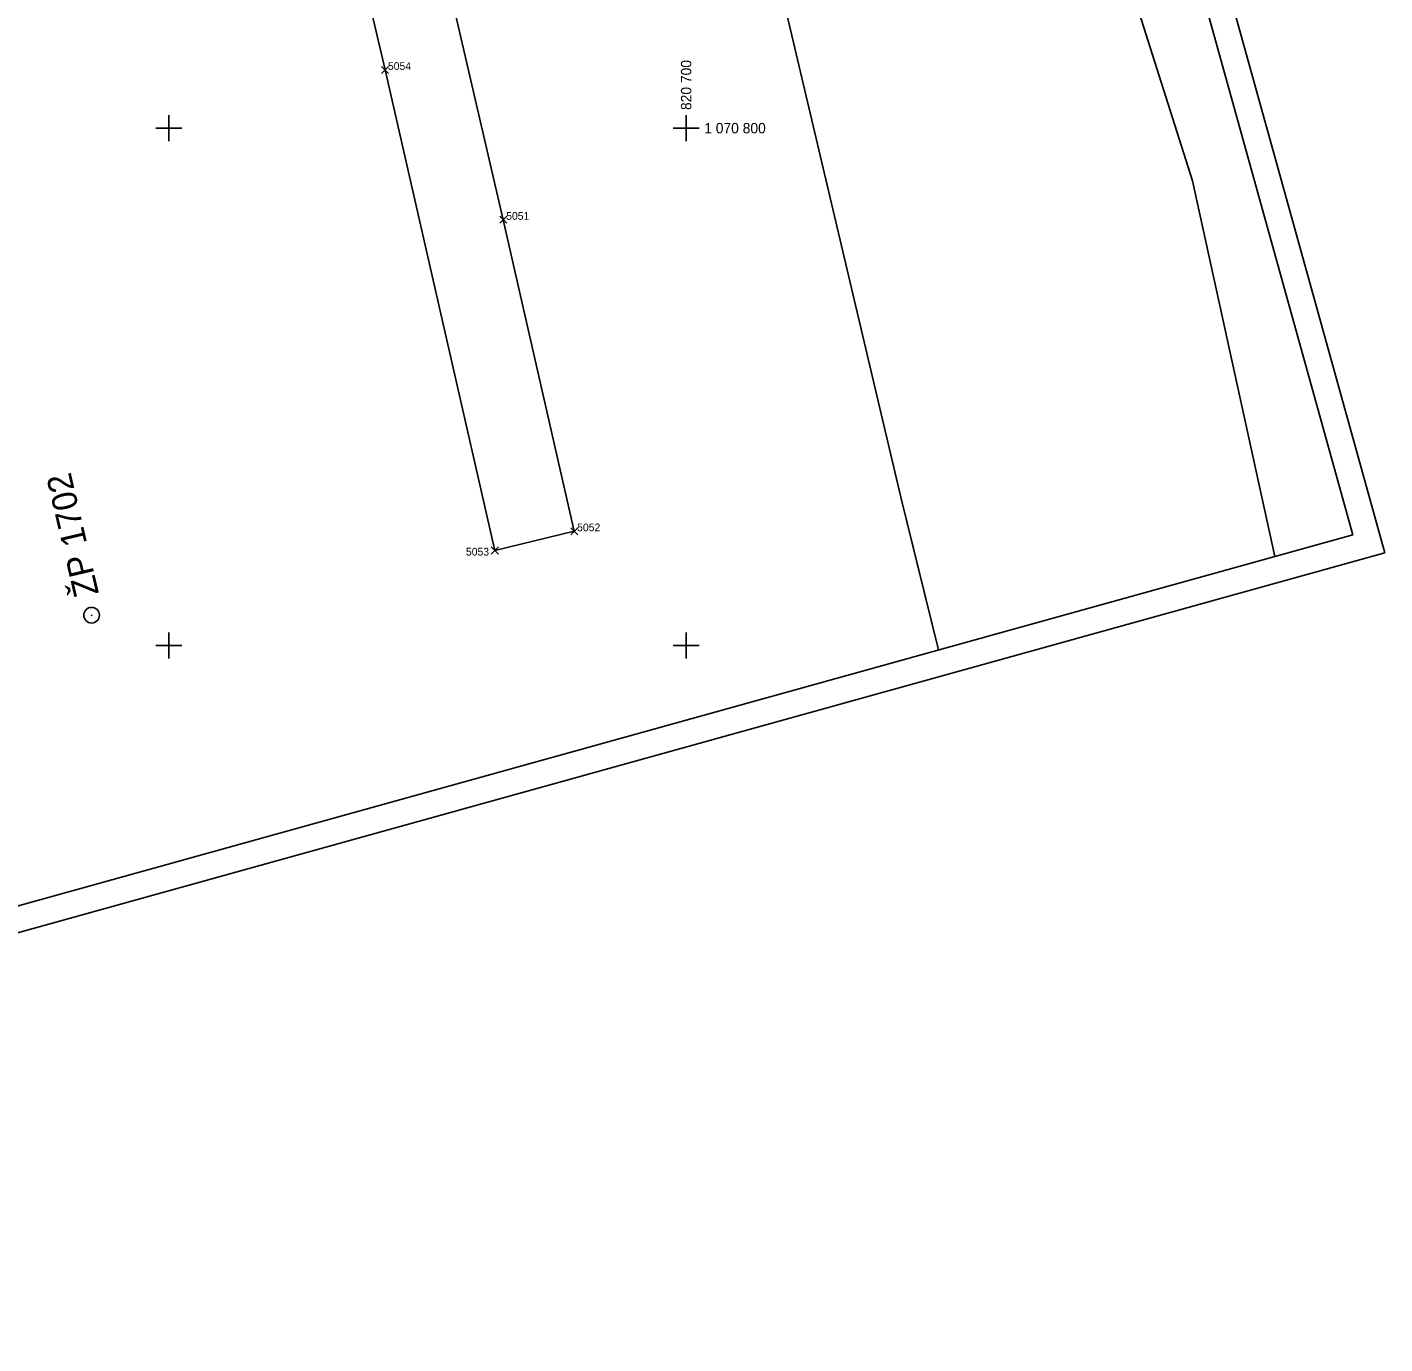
# Model space of a CAD drawing. Extents: x -821172 to -820632, y -1070921 to -1069931.
# Drawn here: x -820763.7 to -820632.5, y -1070917.5 to -1070790.2 of the extents above; entities that cross this region are included whole.
import ezdxf

# ---------------------------------------------------------------- set-up
doc = ezdxf.new("R2010")
doc.units = 0
for name, color, linetype in [('Ram', 7, 'Continuous'), ('Sit', 7, 'Continuous'), ('VB_bod_DZ', 7, 'Continuous'), ('Vrstva 52', 7, 'Continuous'), ('Vrstva 53', 7, 'Continuous'), ('Vrstva 55', 7, 'Continuous'), ('ZBP', 7, 'Continuous')]:
    doc.layers.add(name, color=color, linetype=linetype)

msp = doc.modelspace()

# ---------------------------------------------------------------- linework, layer by layer
at = {"layer": 'Ram'}
for points in [[(-820857.35, -1070031.72), (-820632.46, -1070841.06)], [(-820859.09, -1070034.8), (-820635.54, -1070839.32), (-820916.88, -1070917.49)], [(-820632.46, -1070841.06), (-820775.54, -1070880.81)]]:
    msp.add_lwpolyline(points, dxfattribs=at)
at = {"layer": 'Sit'}
for p, q in [((-820750, -1070798.75), (-820750, -1070800)), ((-820700, -1070798.75), (-820700, -1070800)), ((-820751.25, -1070800), (-820750, -1070800)), ((-820748.75, -1070800), (-820750, -1070800)), ((-820750, -1070801.25), (-820750, -1070800)), ((-820701.25, -1070800), (-820700, -1070800)), ((-820698.75, -1070800), (-820700, -1070800)), ((-820700, -1070801.25), (-820700, -1070800)), ((-820750, -1070848.75), (-820750, -1070850)), ((-820700, -1070848.75), (-820700, -1070850)), ((-820751.25, -1070850), (-820750, -1070850)), ((-820748.75, -1070850), (-820750, -1070850)), ((-820750, -1070851.25), (-820750, -1070850)), ((-820701.25, -1070850), (-820700, -1070850)), ((-820698.75, -1070850), (-820700, -1070850)), ((-820700, -1070851.25), (-820700, -1070850))]:
    msp.add_line(p, q, dxfattribs=at)
at = {"layer": 'VB_bod_DZ'}
for p, q in [((-820729.44, -1070794.72), (-820728.76, -1070794.04)), ((-820728.76, -1070794.72), (-820729.44, -1070794.04)), ((-820718.01, -1070809.2), (-820717.33, -1070808.52)), ((-820717.33, -1070809.2), (-820718.01, -1070808.52)), ((-820711.15, -1070839.31), (-820710.47, -1070838.62)), ((-820710.47, -1070839.31), (-820711.15, -1070838.62)), ((-820718.83, -1070841.17), (-820718.15, -1070840.48)), ((-820718.15, -1070841.17), (-820718.83, -1070840.48))]:
    msp.add_line(p, q, dxfattribs=at)
at = {"layer": 'Vrstva 52'}
msp.add_lwpolyline([(-820753.84, -1070657.98), (-820750.47, -1070669.89), (-820746.26, -1070680.97), (-820737.78, -1070703.32), (-820734.63, -1070715.91), (-820728.44, -1070746.18), (-820726.51, -1070765.13), (-820725.16, -1070774.41), (-820722.68, -1070787.32), (-820717.67, -1070808.86), (-820710.81, -1070838.96), (-820718.49, -1070840.82), (-820729.1, -1070794.38), (-820755.08, -1070683.79), (-820766.7, -1070635.67)], dxfattribs=at)
at = {"layer": 'Vrstva 53'}
msp.add_lwpolyline([(-820720.44, -1070572.46), (-820743.88, -1070569.76), (-820732.22, -1070617.16), (-820718.37, -1070673.87), (-820707.85, -1070716.96), (-820694.56, -1070770.81), (-820679.24, -1070835.68), (-820677.73, -1070841.82), (-820675.61, -1070850.43)], dxfattribs=at)
at = {"layer": 'Vrstva 55'}
for points in [[(-820720.44, -1070572.46), (-820743.88, -1070569.76), (-820732.22, -1070617.16), (-820718.37, -1070673.87), (-820707.85, -1070716.96), (-820694.56, -1070770.81), (-820679.24, -1070835.68), (-820675.61, -1070850.43)], [(-820643.09, -1070841.4), (-820651.05, -1070805.08), (-820667.4, -1070753.6), (-820685.24, -1070696.04), (-820706.9, -1070628.02), (-820713.28, -1070601.74), (-820720.44, -1070572.46)]]:
    msp.add_lwpolyline(points, dxfattribs=at)
at = {"layer": 'ZBP'}
msp.add_line((-820757.46, -1070847.12), (-820757.48, -1070847.03), dxfattribs=at)
msp.add_circle((-820757.47, -1070847.07), 0.756, dxfattribs=at)

# ---------------------------------------------------------------- texts
at = {"layer": 'Sit'}
msp.add_text('820 700', height=1, rotation=90, dxfattribs=at).set_placement((-820699.5, -1070798.25))
msp.add_text('1 070 800', height=1, dxfattribs=at).set_placement((-820698.25, -1070800.5))
at = {"layer": 'VB_bod_DZ'}
for s, p in [(' 5054', (-820729.1, -1070794.38)), (' 5051', (-820717.67, -1070808.86)), (' 5052', (-820710.81, -1070838.96)), (' 5053', (-820721.56, -1070841.31))]:
    msp.add_text(s, height=0.75, dxfattribs=at).set_placement(p)
at = {"layer": 'ZBP'}
msp.add_text('ŽP 1702', height=2.4, rotation=103.1722, dxfattribs=at).set_placement((-820756.75, -1070844.98))

doc.saveas('drawing.dxf')
